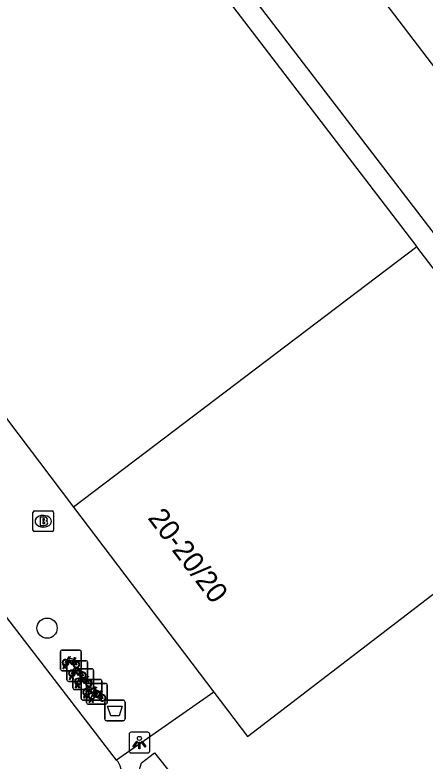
# Model space of a CAD drawing. Extents: x 160158 to 160921, y 381517 to 382041.
# Drawn here: x 160223.34 to 160243.22, y 381600.88 to 381637.02 of the extents above; entities that cross this region are included whole.
import ezdxf

# ---------------------------------------------------------------- set-up
doc = ezdxf.new("R2010")
doc.units = 0
for name, color, linetype in [('IMGEO_Afvalbak', 7, 'Continuous'), ('IMGEO_Boom', 7, 'Continuous'), ('IMGEO_Brandkraan', 7, 'Continuous'), ('IMGEO_Fietsenrek', 7, 'Continuous'), ('IMGEO_Lichtpunt', 7, 'Continuous'), ('IMGEO_Pand', 7, 'Continuous'), ('IMGEO_Pand_nummerreeks', 7, 'Continuous'), ('IMGEO_Rijbaan_lokaal_open', 7, 'Continuous'), ('IMGEO_Voetpad_open', 7, 'Continuous')]:
    doc.layers.add(name, color=color, linetype=linetype)

msp = doc.modelspace()

# ---------------------------------------------------------------- linework, layer by layer
at = {"layer": 'IMGEO_Afvalbak'}
for p, q in [((160227.687, 381602.932), (160227.687, 381603.732)), ((160227.687, 381603.732), (160227.687, 381602.932)), ((160227.787, 381603.832), (160228.577, 381603.832)), ((160228.577, 381603.832), (160227.787, 381603.832)), ((160228.677, 381603.732), (160228.677, 381602.932)), ((160228.677, 381602.932), (160228.677, 381603.732)), ((160228.577, 381602.832), (160227.787, 381602.832)), ((160227.787, 381602.832), (160228.577, 381602.832))]:
    msp.add_line(p, q, dxfattribs=at)
msp.add_lwpolyline([(160227.83, 381603.546), (160228.534, 381603.546), (160228.385, 381603.076), (160227.979, 381603.076), (160227.83, 381603.546)], dxfattribs=at)
for centre, start, end in [((160227.787, 381603.732), 90, 180), ((160227.787, 381603.732), 90, 180), ((160228.577, 381603.732), 0, 90), ((160228.577, 381603.732), 360, 90), ((160227.787, 381602.932), 180, 270), ((160227.787, 381602.932), 180, 270), ((160228.577, 381602.932), 270, 0), ((160228.577, 381602.932), 270, 0)]:
    msp.add_arc(centre, 0.1, start, end, dxfattribs=at)
at = {"layer": 'IMGEO_Boom'}
msp.add_circle((160224.895, 381607.32), 0.489, dxfattribs=at)
at = {"layer": 'IMGEO_Brandkraan'}
for p, q in [((160224.285, 381612.997), (160225.137, 381612.997)), ((160224.21, 381612.071), (160224.21, 381612.923)), ((160224.698, 381612.777), (160224.723, 381612.777)), ((160225.211, 381612.923), (160225.211, 381612.071)), ((160225.137, 381611.997), (160224.285, 381611.997)), ((160224.721, 381612.217), (160224.696, 381612.217))]:
    msp.add_line(p, q, dxfattribs=at)
for points in [[(160224.285, 381612.997), (160225.137, 381612.997)], [(160224.21, 381612.071), (160224.21, 381612.923)], [(160224.558, 381612.697), (160224.558, 381612.297), (160224.771, 381612.297)], [(160224.789, 381612.697), (160224.558, 381612.697)], [(160225.211, 381612.923), (160225.211, 381612.071)], [(160224.737, 381612.616), (160224.683, 381612.616), (160224.683, 381612.54)], [(160224.683, 381612.54), (160224.736, 381612.54)], [(160224.745, 381612.464), (160224.683, 381612.464), (160224.683, 381612.383)], [(160224.683, 381612.383), (160224.745, 381612.383)], [(160225.137, 381611.997), (160224.285, 381611.997)]]:
    msp.add_lwpolyline(points, dxfattribs=at)
for centre, radius, start, end in [((160224.287, 381612.921), 0.0765, 91.552, 178.448), ((160224.287, 381612.921), 0.0765, 91.552, 178.448), ((160225.135, 381612.921), 0.0765, 1.552, 88.448), ((160225.135, 381612.921), 0.0765, 1.552, 88.448), ((160224.793, 381612.552), 0.145, 59.4692, 91.5367), ((160224.818, 381612.599), 0.0922, 285.5137, 58.1501), ((160224.738, 381612.578), 0.0379, 267.8285, 90.9355), ((160224.746, 381612.423), 0.0404, 269.8759, 90.5077), ((160224.777, 381612.548), 0.251, 268.6676, 293.5347), ((160224.823, 381612.407), 0.105, 301.3115, 78.989), ((160224.287, 381612.073), 0.0765, 181.552, 268.448), ((160224.287, 381612.073), 0.0765, 181.552, 268.448), ((160225.135, 381612.073), 0.0765, 271.552, 358.448), ((160225.135, 381612.073), 0.0765, 271.552, 358.448)]:
    msp.add_arc(centre, radius, start, end, dxfattribs=at)
for centre, major_axis, ratio, start_param, end_param in [((160224.697, 381612.497), (-0.387, 0.002), 0.722429, 4.712389, 7.853982), ((160224.722, 381612.497), (-0.39, 0.002), 0.717154, 1.570796, 4.712389)]:
    msp.add_ellipse(centre, major_axis=major_axis, ratio=ratio, start_param=start_param, end_param=end_param, dxfattribs=at)
at = {"layer": 'IMGEO_Fietsenrek'}
for p, q in [((160225.548, 381605.331), (160225.548, 381606.172)), ((160225.548, 381606.172), (160225.548, 381605.331)), ((160225.623, 381606.256), (160226.464, 381606.256)), ((160226.464, 381606.256), (160225.623, 381606.256)), ((160226.548, 381606.181), (160226.548, 381605.34)), ((160226.548, 381605.34), (160226.548, 381606.181)), ((160226.235, 381605.805), (160226.271, 381605.71)), ((160225.675, 381605.34), (160225.714, 381605.5)), ((160225.744, 381605.488), (160225.709, 381605.34)), ((160225.786, 381605.512), (160225.785, 381605.516)), ((160225.827, 381605.34), (160225.793, 381605.482)), ((160225.817, 381605.523), (160225.818, 381605.516)), ((160225.825, 381605.486), (160225.86, 381605.34)), ((160225.858, 381604.814), (160225.858, 381605.655)), ((160225.858, 381605.655), (160225.858, 381604.814)), ((160225.933, 381605.739), (160226.774, 381605.739)), ((160226.774, 381605.739), (160225.933, 381605.739)), ((160226.858, 381605.664), (160226.858, 381604.823)), ((160226.858, 381604.823), (160226.858, 381605.664)), ((160226.473, 381605.256), (160225.632, 381605.256)), ((160225.632, 381605.256), (160226.473, 381605.256)), ((160225.709, 381605.34), (160225.675, 381605.34)), ((160225.86, 381605.34), (160225.827, 381605.34)), ((160226.146, 381604.423), (160226.146, 381605.264)), ((160226.146, 381605.264), (160226.146, 381604.423)), ((160226.221, 381605.348), (160227.062, 381605.348)), ((160227.062, 381605.348), (160226.221, 381605.348)), ((160226.545, 381605.288), (160226.581, 381605.193)), ((160227.146, 381605.273), (160227.146, 381604.432)), ((160227.146, 381604.432), (160227.146, 381605.273)), ((160226.783, 381604.739), (160225.942, 381604.739)), ((160225.942, 381604.739), (160226.783, 381604.739)), ((160225.985, 381604.823), (160226.024, 381604.983)), ((160226.019, 381604.823), (160225.985, 381604.823)), ((160226.054, 381604.971), (160226.019, 381604.823)), ((160226.096, 381604.995), (160226.095, 381604.999)), ((160226.137, 381604.823), (160226.103, 381604.965)), ((160226.127, 381605.006), (160226.128, 381604.999)), ((160226.135, 381604.969), (160226.17, 381604.823)), ((160226.17, 381604.823), (160226.137, 381604.823)), ((160226.547, 381603.911), (160226.547, 381604.752)), ((160226.547, 381604.752), (160226.547, 381603.911)), ((160226.622, 381604.836), (160227.463, 381604.836)), ((160227.463, 381604.836), (160226.622, 381604.836)), ((160226.833, 381604.897), (160226.869, 381604.802)), ((160227.547, 381604.761), (160227.547, 381603.92)), ((160227.547, 381603.92), (160227.547, 381604.761)), ((160227.071, 381604.348), (160226.23, 381604.348)), ((160226.23, 381604.348), (160227.071, 381604.348)), ((160226.273, 381604.432), (160226.312, 381604.592)), ((160226.307, 381604.432), (160226.273, 381604.432)), ((160226.342, 381604.58), (160226.307, 381604.432)), ((160226.384, 381604.604), (160226.383, 381604.608)), ((160226.425, 381604.432), (160226.391, 381604.574)), ((160226.415, 381604.615), (160226.416, 381604.608)), ((160226.423, 381604.578), (160226.458, 381604.432)), ((160226.458, 381604.432), (160226.425, 381604.432)), ((160226.813, 381603.712), (160226.813, 381604.553)), ((160226.813, 381604.553), (160226.813, 381603.712)), ((160226.888, 381604.637), (160227.729, 381604.637)), ((160227.729, 381604.637), (160226.888, 381604.637)), ((160227.234, 381604.385), (160227.27, 381604.29)), ((160227.813, 381604.562), (160227.813, 381603.721)), ((160227.813, 381603.721), (160227.813, 381604.562)), ((160226.674, 381603.92), (160226.713, 381604.08)), ((160226.743, 381604.068), (160226.708, 381603.92)), ((160226.785, 381604.092), (160226.784, 381604.096)), ((160226.826, 381603.92), (160226.792, 381604.062)), ((160226.816, 381604.103), (160226.817, 381604.096)), ((160226.824, 381604.066), (160226.859, 381603.92)), ((160227.5, 381604.186), (160227.536, 381604.091)), ((160227.472, 381603.836), (160226.631, 381603.836)), ((160226.631, 381603.836), (160227.472, 381603.836)), ((160226.708, 381603.92), (160226.674, 381603.92)), ((160226.859, 381603.92), (160226.826, 381603.92)), ((160227.738, 381603.637), (160226.897, 381603.637)), ((160226.897, 381603.637), (160227.738, 381603.637)), ((160226.94, 381603.721), (160226.979, 381603.881)), ((160226.974, 381603.721), (160226.94, 381603.721)), ((160227.009, 381603.869), (160226.974, 381603.721)), ((160227.051, 381603.893), (160227.05, 381603.897)), ((160227.092, 381603.721), (160227.058, 381603.863)), ((160227.082, 381603.904), (160227.083, 381603.897)), ((160227.09, 381603.867), (160227.125, 381603.721)), ((160227.125, 381603.721), (160227.092, 381603.721))]:
    msp.add_line(p, q, dxfattribs=at)
for points in [[(160225.882, 381605.73), (160225.83, 381605.64), (160225.79, 381605.615), (160225.791, 381605.662), (160225.846, 381605.756)], [(160225.861, 381605.782), (160225.956, 381605.946), (160226.042, 381605.932), (160226.044, 381605.923), (160225.988, 381605.912), (160225.961, 381605.867), (160226.217, 381605.826)], [(160226.157, 381605.538), (160226.107, 381605.538), (160225.916, 381605.789), (160225.897, 381605.757)], [(160226.204, 381605.801), (160225.947, 381605.842), (160225.93, 381605.813), (160226.097, 381605.593), (160226.204, 381605.801)], [(160226.252, 381605.703), (160226.222, 381605.78), (160226.113, 381605.562), (160226.156, 381605.562)], [(160226.217, 381605.826), (160226.242, 381605.875), (160226.236, 381605.879), (160226.213, 381605.883), (160226.201, 381605.89), (160226.2, 381605.893), (160226.202, 381605.898), (160226.297, 381605.883), (160226.299, 381605.873), (160226.289, 381605.86), (160226.277, 381605.854), (160226.263, 381605.86), (160226.235, 381605.805)], [(160226.171, 381605.265), (160226.266, 381605.429), (160226.352, 381605.415), (160226.354, 381605.406), (160226.298, 381605.395), (160226.271, 381605.35), (160226.527, 381605.309)], [(160226.186, 381605.562), (160226.306, 381605.561), (160226.262, 381605.675)], [(160226.282, 381605.682), (160226.337, 381605.537), (160226.187, 381605.537)], [(160226.192, 381605.213), (160226.14, 381605.123), (160226.1, 381605.098), (160226.101, 381605.145), (160226.156, 381605.239)], [(160226.467, 381605.021), (160226.417, 381605.021), (160226.226, 381605.272), (160226.207, 381605.24)], [(160226.514, 381605.284), (160226.257, 381605.325), (160226.24, 381605.296), (160226.407, 381605.076), (160226.514, 381605.284)], [(160226.562, 381605.186), (160226.532, 381605.263), (160226.423, 381605.045), (160226.466, 381605.045)], [(160226.459, 381604.874), (160226.554, 381605.038), (160226.64, 381605.024), (160226.642, 381605.015), (160226.586, 381605.004), (160226.559, 381604.959), (160226.815, 381604.918)], [(160226.496, 381605.045), (160226.616, 381605.044), (160226.572, 381605.158)], [(160226.592, 381605.165), (160226.647, 381605.02), (160226.497, 381605.02)], [(160226.527, 381605.309), (160226.552, 381605.358), (160226.546, 381605.362), (160226.523, 381605.366), (160226.511, 381605.373), (160226.51, 381605.376), (160226.512, 381605.381), (160226.607, 381605.366), (160226.609, 381605.356), (160226.599, 381605.343), (160226.587, 381605.337), (160226.573, 381605.343), (160226.545, 381605.288)], [(160226.48, 381604.822), (160226.428, 381604.732), (160226.388, 381604.707), (160226.389, 381604.754), (160226.444, 381604.848)], [(160226.755, 381604.63), (160226.705, 381604.63), (160226.514, 381604.881), (160226.495, 381604.849)], [(160226.802, 381604.893), (160226.545, 381604.934), (160226.528, 381604.905), (160226.695, 381604.685), (160226.802, 381604.893)], [(160226.85, 381604.795), (160226.82, 381604.872), (160226.711, 381604.654), (160226.754, 381604.654)], [(160226.784, 381604.654), (160226.904, 381604.653), (160226.86, 381604.767)], [(160226.88, 381604.774), (160226.935, 381604.629), (160226.785, 381604.629)], [(160226.815, 381604.918), (160226.84, 381604.967), (160226.834, 381604.971), (160226.811, 381604.975), (160226.799, 381604.982), (160226.798, 381604.985), (160226.8, 381604.99), (160226.895, 381604.975), (160226.897, 381604.965), (160226.887, 381604.952), (160226.875, 381604.946), (160226.861, 381604.952), (160226.833, 381604.897)], [(160226.881, 381604.31), (160226.829, 381604.22), (160226.789, 381604.195), (160226.79, 381604.242), (160226.845, 381604.336)], [(160226.86, 381604.362), (160226.955, 381604.526), (160227.041, 381604.512), (160227.043, 381604.503), (160226.987, 381604.492), (160226.96, 381604.447), (160227.216, 381604.406)], [(160227.156, 381604.118), (160227.106, 381604.118), (160226.915, 381604.369), (160226.896, 381604.337)], [(160227.203, 381604.381), (160226.946, 381604.422), (160226.929, 381604.393), (160227.096, 381604.173), (160227.203, 381604.381)], [(160227.251, 381604.283), (160227.221, 381604.36), (160227.112, 381604.142), (160227.155, 381604.142)], [(160227.126, 381604.163), (160227.221, 381604.327), (160227.307, 381604.313), (160227.309, 381604.304), (160227.253, 381604.293), (160227.226, 381604.248), (160227.482, 381604.207)], [(160227.216, 381604.406), (160227.241, 381604.455), (160227.235, 381604.459), (160227.212, 381604.463), (160227.2, 381604.47), (160227.199, 381604.473), (160227.201, 381604.478), (160227.296, 381604.463), (160227.298, 381604.453), (160227.288, 381604.44), (160227.276, 381604.434), (160227.262, 381604.44), (160227.234, 381604.385)], [(160227.147, 381604.111), (160227.095, 381604.021), (160227.055, 381603.996), (160227.056, 381604.043), (160227.111, 381604.137)], [(160227.422, 381603.919), (160227.372, 381603.919), (160227.181, 381604.17), (160227.162, 381604.138)], [(160227.185, 381604.142), (160227.305, 381604.141), (160227.261, 381604.255)], [(160227.281, 381604.262), (160227.336, 381604.117), (160227.186, 381604.117)], [(160227.469, 381604.182), (160227.212, 381604.223), (160227.195, 381604.194), (160227.362, 381603.974), (160227.469, 381604.182)], [(160227.517, 381604.084), (160227.487, 381604.161), (160227.378, 381603.943), (160227.421, 381603.943)], [(160227.451, 381603.943), (160227.571, 381603.942), (160227.527, 381604.056)], [(160227.547, 381604.063), (160227.602, 381603.918), (160227.452, 381603.918)], [(160227.482, 381604.207), (160227.507, 381604.256), (160227.501, 381604.26), (160227.478, 381604.264), (160227.466, 381604.271), (160227.465, 381604.274), (160227.467, 381604.279), (160227.562, 381604.264), (160227.564, 381604.254), (160227.554, 381604.241), (160227.542, 381604.235), (160227.528, 381604.241), (160227.5, 381604.186)]]:
    msp.add_lwpolyline(points, dxfattribs=at)
for centre, radius, start, end in [((160225.626, 381606.178), 0.0779, 92.4484, 184.2845), ((160225.626, 381606.178), 0.0779, 92.4484, 184.2845), ((160226.47, 381606.178), 0.0779, 2.4484, 94.2845), ((160226.47, 381606.178), 0.0779, 2.4484, 94.2845), ((160225.788, 381605.641), 0.159, 62.6766, 242.1369), ((160225.788, 381605.641), 0.129, 63.3192, 238.903), ((160225.788, 381605.641), 0.159, 283.5766, 46.6042), ((160225.768, 381605.512), 0.0499, 12.8025, 158.6934), ((160225.788, 381605.641), 0.159, 253.9967, 271.7867), ((160225.768, 381605.512), 0.0174, 12.8025, 163.4502), ((160225.788, 381605.641), 0.129, 253.415, 269.0204), ((160225.788, 381605.641), 0.129, 283.6043, 43.4302), ((160225.936, 381605.661), 0.0779, 92.4484, 184.2845), ((160225.936, 381605.661), 0.0779, 92.4484, 184.2845), ((160226.315, 381605.557), 0.159, 113.3408, 178.3217), ((160226.315, 381605.557), 0.159, 187.0065, 105.7708), ((160226.315, 381605.557), 0.129, 113.923, 177.9556), ((160226.315, 381605.557), 0.129, 188.6715, 104.5883), ((160226.78, 381605.661), 0.0779, 2.4484, 94.2845), ((160226.78, 381605.661), 0.0779, 2.4484, 94.2845), ((160225.626, 381605.334), 0.0779, 182.4484, 274.2845), ((160225.626, 381605.334), 0.0779, 182.4484, 274.2845), ((160226.098, 381605.124), 0.159, 62.6766, 242.1369), ((160226.098, 381605.124), 0.129, 63.3192, 238.903), ((160226.078, 381604.995), 0.0499, 12.8025, 158.6934), ((160226.098, 381605.124), 0.129, 283.6043, 43.4302), ((160226.098, 381605.124), 0.159, 283.5766, 46.6042), ((160226.224, 381605.27), 0.0779, 92.4484, 184.2845), ((160226.224, 381605.27), 0.0779, 92.4484, 184.2845), ((160226.625, 381605.04), 0.159, 113.3408, 178.3217), ((160226.625, 381605.04), 0.159, 187.0065, 105.7708), ((160226.47, 381605.334), 0.0779, 272.4484, 4.2845), ((160226.47, 381605.334), 0.0779, 272.4484, 4.2845), ((160226.625, 381605.04), 0.129, 113.923, 177.9556), ((160226.625, 381605.04), 0.129, 188.6715, 104.5883), ((160227.068, 381605.27), 0.0779, 2.4484, 94.2845), ((160227.068, 381605.27), 0.0779, 2.4484, 94.2845), ((160225.936, 381604.817), 0.0779, 182.4484, 274.2845), ((160225.936, 381604.817), 0.0779, 182.4484, 274.2845), ((160226.098, 381605.124), 0.159, 253.9967, 271.7867), ((160226.078, 381604.995), 0.0174, 12.8025, 163.4502), ((160226.098, 381605.124), 0.129, 253.415, 269.0204), ((160226.386, 381604.733), 0.159, 62.6766, 242.1369), ((160226.386, 381604.733), 0.129, 63.3192, 238.903), ((160226.386, 381604.733), 0.129, 283.6043, 43.4302), ((160226.386, 381604.733), 0.159, 283.5766, 46.6042), ((160226.625, 381604.758), 0.0779, 92.4484, 184.2845), ((160226.625, 381604.758), 0.0779, 92.4484, 184.2845), ((160226.913, 381604.649), 0.159, 113.3408, 178.3217), ((160226.913, 381604.649), 0.159, 187.0065, 105.7708), ((160226.78, 381604.817), 0.0779, 272.4484, 4.2845), ((160226.78, 381604.817), 0.0779, 272.4484, 4.2845), ((160226.913, 381604.649), 0.129, 113.923, 177.9556), ((160226.913, 381604.649), 0.129, 188.6715, 104.5883), ((160227.469, 381604.758), 0.0779, 2.4484, 94.2845), ((160227.469, 381604.758), 0.0779, 2.4484, 94.2845), ((160226.224, 381604.426), 0.0779, 182.4484, 274.2845), ((160226.224, 381604.426), 0.0779, 182.4484, 274.2845), ((160226.366, 381604.604), 0.0499, 12.8025, 158.6934), ((160226.386, 381604.733), 0.159, 253.9967, 271.7867), ((160226.366, 381604.604), 0.0174, 12.8025, 163.4502), ((160226.386, 381604.733), 0.129, 253.415, 269.0204), ((160226.787, 381604.221), 0.159, 62.6766, 242.1369), ((160226.787, 381604.221), 0.129, 63.3192, 238.903), ((160226.891, 381604.559), 0.0779, 92.4484, 184.2845), ((160226.891, 381604.559), 0.0779, 92.4484, 184.2845), ((160226.787, 381604.221), 0.129, 283.6043, 43.4302), ((160226.787, 381604.221), 0.159, 283.5766, 46.6042), ((160227.068, 381604.426), 0.0779, 272.4484, 4.2845), ((160227.068, 381604.426), 0.0779, 272.4484, 4.2845), ((160227.735, 381604.559), 0.0779, 2.4484, 94.2845), ((160227.735, 381604.559), 0.0779, 2.4484, 94.2845), ((160226.767, 381604.092), 0.0499, 12.8025, 158.6934), ((160226.787, 381604.221), 0.159, 253.9967, 271.7867), ((160226.767, 381604.092), 0.0174, 12.8025, 163.4502), ((160226.787, 381604.221), 0.129, 253.415, 269.0204), ((160227.053, 381604.022), 0.159, 62.6766, 242.1369), ((160227.053, 381604.022), 0.129, 63.3192, 238.903), ((160227.053, 381604.022), 0.129, 283.6043, 43.4302), ((160227.053, 381604.022), 0.159, 283.5766, 46.6042), ((160227.314, 381604.137), 0.159, 113.3408, 178.3217), ((160227.314, 381604.137), 0.159, 187.0065, 105.7708), ((160227.314, 381604.137), 0.129, 113.923, 177.9556), ((160227.314, 381604.137), 0.129, 188.6715, 104.5883), ((160227.58, 381603.938), 0.159, 113.3408, 178.3217), ((160227.58, 381603.938), 0.159, 187.0065, 105.7708), ((160227.58, 381603.938), 0.129, 113.923, 177.9556), ((160227.58, 381603.938), 0.129, 188.6715, 104.5883), ((160226.625, 381603.914), 0.0779, 182.4484, 274.2845), ((160226.625, 381603.914), 0.0779, 182.4484, 274.2845), ((160226.891, 381603.715), 0.0779, 182.4484, 274.2845), ((160226.891, 381603.715), 0.0779, 182.4484, 274.2845), ((160227.033, 381603.893), 0.0499, 12.8025, 158.6934), ((160227.053, 381604.022), 0.159, 253.9967, 271.7867), ((160227.033, 381603.893), 0.0174, 12.8025, 163.4502), ((160227.053, 381604.022), 0.129, 253.415, 269.0204), ((160227.469, 381603.914), 0.0779, 272.4484, 4.2845), ((160227.469, 381603.914), 0.0779, 272.4484, 4.2845), ((160227.735, 381603.715), 0.0779, 272.4484, 4.2845), ((160227.735, 381603.715), 0.0779, 272.4484, 4.2845)]:
    msp.add_arc(centre, radius, start, end, dxfattribs=at)
at = {"layer": 'IMGEO_Lichtpunt'}
for p, q in [((160228.872, 381602.178), (160228.872, 381601.371)), ((160228.872, 381602.178), (160228.872, 381601.371)), ((160229.774, 381602.273), (160228.966, 381602.273)), ((160229.774, 381602.273), (160228.966, 381602.273)), ((160229.868, 381601.371), (160229.868, 381602.178)), ((160229.868, 381601.371), (160229.868, 381602.178)), ((160228.966, 381601.277), (160229.774, 381601.277)), ((160228.966, 381601.277), (160229.774, 381601.277))]:
    msp.add_line(p, q, dxfattribs=at)
for points in [[(160229.246, 381601.842), (160229.285, 381601.814), (160229.097, 381601.552), (160229.059, 381601.579), (160229.246, 381601.842)], [(160229.348, 381601.794), (160229.395, 381601.794), (160229.395, 381601.472), (160229.348, 381601.472), (160229.348, 381601.794)], [(160229.458, 381601.814), (160229.496, 381601.841), (160229.683, 381601.579), (160229.644, 381601.551), (160229.458, 381601.814)]]:
    msp.add_lwpolyline(points, dxfattribs=at)
msp.add_circle((160229.371, 381601.976), 0.0994, dxfattribs=at)
for centre, start, end in [((160228.966, 381602.178), 90, 180), ((160228.966, 381602.178), 90, 180), ((160229.774, 381602.178), 0, 90), ((160229.774, 381602.178), 0, 90), ((160228.966, 381601.371), 180, 270), ((160228.966, 381601.371), 180, 270), ((160229.774, 381601.371), 270, 0), ((160229.774, 381601.371), 270, 360)]:
    msp.add_arc(centre, 0.0946, start, end, dxfattribs=at)
at = {"layer": 'IMGEO_Pand'}
for points in [[(160229.025, 381643.813), (160242.824, 381625.788)], [(160212.568, 381631.144), (160226.18, 381613.178)], [(160242.824, 381625.788), (160226.18, 381613.178)], [(160232.975, 381604.21), (160234.601, 381602.064), (160251.229, 381614.81), (160249.159, 381617.513), (160242.824, 381625.788)], [(160226.18, 381613.178), (160232.975, 381604.21)]]:
    msp.add_lwpolyline(points, dxfattribs=at)
at = {"layer": 'IMGEO_Rijbaan_lokaal_open'}
for points in [[(160224.171, 381650.152), (160226.57, 381651.942), (160228.618, 381652.681), (160229.719, 381652.76), (160246.171, 381631.2)], [(160252.688, 381614.66), (160250.004, 381618.161), (160230.499, 381643.584)]]:
    msp.add_lwpolyline(points, dxfattribs=at)
at = {"layer": 'IMGEO_Voetpad_open'}
for points in [[(160228.264, 381600.92), (160200.851, 381636.528)], [(160232.975, 381604.21), (160228.264, 381600.92)], [(160228.706, 381596.593), (160228.347, 381597.054), (160229.466, 381600.798), (160230.097, 381601.273), (160231.877, 381599.046), (160228.706, 381596.593)]]:
    msp.add_lwpolyline(points, dxfattribs=at)
msp.add_arc((160227.629, 381600.319), 0.875, 345.8683, 43.425, dxfattribs=at)

# ---------------------------------------------------------------- texts
at = {"layer": 'IMGEO_Pand_nummerreeks'}
msp.add_text('20-20/20', height=1, rotation=307.1504, dxfattribs=at).set_placement((160229.744, 381612.648))

doc.saveas('drawing.dxf')
